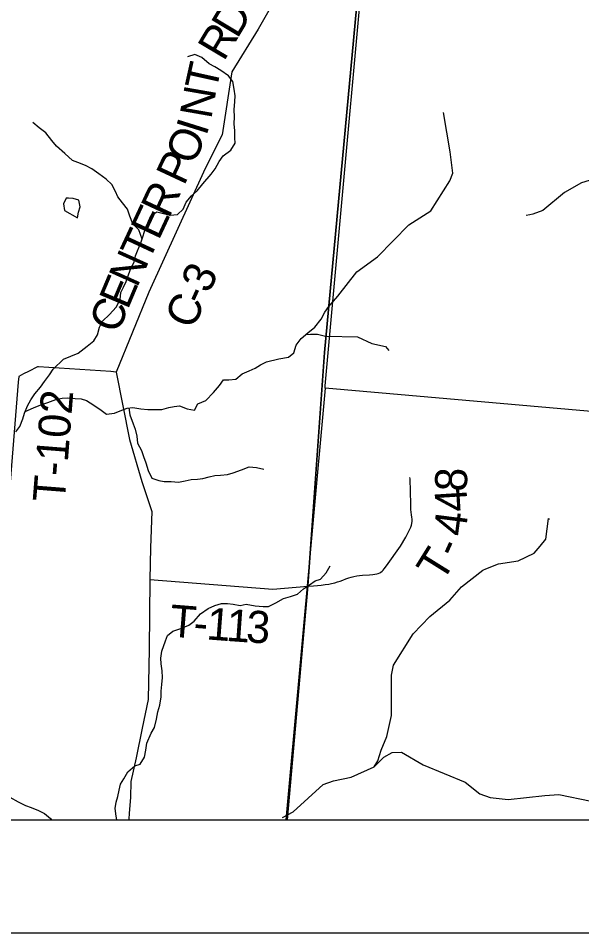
# Model space of a CAD drawing. Extents: x 0 to 42, y 0 to 22.
# Drawn here: x 7.812 to 8.311, y 14 to 14.81 of the extents above; entities that cross this region are included whole.
import ezdxf

# ---------------------------------------------------------------- set-up
doc = ezdxf.new("R2010")
doc.units = 0
for name, color, linetype in [('GM_X_County_Road', 7, 'Continuous'), ('GM_X_County_Road_Text', 7, 'Continuous'), ('GM_X_Minor_Lake', 7, 'Continuous'), ('GM_X_Minor_River', 7, 'Continuous'), ('GM_X_Section', 7, 'Continuous'), ('GM_X_Township_Road', 7, 'Continuous'), ('GM_X_Township_Road_Text', 7, 'Continuous'), ('GM_X_Unincorporated', 7, 'Continuous'), ('SH_Cut_Line', 7, 'Continuous'), ('SH_Data', 7, 'Continuous')]:
    doc.layers.add(name, color=color, linetype=linetype)

msp = doc.modelspace()

# ---------------------------------------------------------------- linework, layer by layer
at = {"layer": 'GM_X_County_Road'}
msp.add_lwpolyline([(8.04723, 14.83957), (8.0246, 14.79994), (8.00131, 14.76235), (7.99271, 14.70653), (7.97771, 14.67652), (7.92772, 14.56724), (7.89891, 14.49644), (7.91067, 14.43677), (7.92151, 14.39947), (7.93053, 14.37298), (7.92917, 14.34086), (7.92863, 14.31266), (7.92805, 14.25119), (7.9272, 14.20636), (7.92197, 14.18103), (7.91656, 14.15495), (7.91186, 14.13381), (7.91144, 14.11975), (7.91045, 14.10587), (7.90994, 14.10055), (7.91011, 14.1)], dxfattribs=at)
at = {"layer": 'GM_X_Minor_Lake'}
for points in [[(7.85646, 14.65026), (7.8546, 14.65038), (7.85197, 14.64544), (7.85292, 14.63937), (7.86447, 14.63295)], [(7.86447, 14.63295), (7.86541, 14.63807), (7.86691, 14.64282), (7.86558, 14.64869), (7.86066, 14.65001), (7.85646, 14.65026)]]:
    msp.add_lwpolyline(points, dxfattribs=at)
at = {"layer": 'GM_X_Minor_River'}
for points in [[(7.86526, 14.51323), (7.87301, 14.51935), (7.87905, 14.52391), (7.88226, 14.52923), (7.88414, 14.53606), (7.88677, 14.54138), (7.893, 14.54746), (7.89866, 14.55373), (7.90225, 14.56057), (7.90299, 14.56683), (7.90544, 14.57157), (7.9077, 14.5767), (7.90958, 14.58239), (7.91222, 14.58885), (7.91486, 14.5936), (7.91598, 14.59929), (7.92087, 14.61163), (7.92276, 14.61694), (7.92444, 14.62302), (7.92746, 14.63004), (7.92953, 14.63479), (7.93482, 14.63821), (7.94655, 14.6352), (7.95317, 14.63597), (7.95827, 14.64053), (7.96071, 14.6468), (7.96562, 14.65231), (7.97053, 14.65687), (7.97562, 14.66314), (7.98298, 14.6715), (7.98657, 14.67625), (7.98996, 14.6829), (7.99354, 14.68783), (8.00034, 14.69278), (8.0043, 14.69905), (8.00411, 14.70379), (8.00409, 14.70986), (8.00333, 14.71631), (8.00369, 14.72238), (8.00349, 14.72844), (8.00386, 14.73603), (8.00423, 14.74097), (8.00346, 14.74684), (8.00231, 14.75367), (7.99833, 14.75878), (7.99151, 14.76332), (7.98621, 14.76654), (7.9811, 14.76937), (7.97466, 14.77486), (7.96841, 14.7775), (7.96198, 14.7754)], [(8.08738, 14.55438), (8.09512, 14.5635), (8.11201, 14.58521), (8.13034, 14.59835), (8.15829, 14.62662), (8.17776, 14.63918), (8.19451, 14.66583), (8.19722, 14.67264), (8.19493, 14.69147), (8.18881, 14.72609)], [(7.92179, 14.6142), (7.91877, 14.62244), (7.91347, 14.62755), (7.91081, 14.63456), (7.9089, 14.64062), (7.90454, 14.64612), (7.90018, 14.65142), (7.89809, 14.65634), (7.89506, 14.66241), (7.88994, 14.66714), (7.8835, 14.67187), (7.87725, 14.67622), (7.87176, 14.67943), (7.86495, 14.68188), (7.86003, 14.68377), (7.85321, 14.68983), (7.84582, 14.69645), (7.84184, 14.70137), (7.83653, 14.70819), (7.83047, 14.71273), (7.82498, 14.71727)], [(8.32187, 14.66733), (8.31109, 14.6639), (8.29616, 14.65534), (8.27707, 14.63956), (8.26818, 14.63632), (8.26534, 14.63555), (8.26232, 14.63498)], [(8.05628, 14.51336), (8.05835, 14.52029), (8.06288, 14.52599), (8.06854, 14.53113), (8.07478, 14.53626), (8.08044, 14.5431), (8.08383, 14.54937), (8.08738, 14.55438)], [(8.06698, 14.52971), (8.071, 14.52999), (8.07725, 14.53001), (8.08425, 14.52831), (8.08514, 14.52831)], [(8.08514, 14.52831), (8.1128, 14.52764), (8.12545, 14.52184), (8.13757, 14.51908), (8.14057, 14.51564)], [(7.8099, 14.4436), (7.81351, 14.44835), (7.81616, 14.45499), (7.81749, 14.45992), (7.82034, 14.46637), (7.82318, 14.47168), (7.82679, 14.477), (7.83172, 14.48307), (7.83532, 14.488), (7.83969, 14.49408), (7.84291, 14.49901), (7.85203, 14.50771), (7.86526, 14.51323)], [(7.81815, 14.46141), (7.82546, 14.46486), (7.8319, 14.46732), (7.83816, 14.46941), (7.84537, 14.47207), (7.85087, 14.47321), (7.85561, 14.47359), (7.86243, 14.47303), (7.86774, 14.47265), (7.87248, 14.47113), (7.87912, 14.46715), (7.88537, 14.4626), (7.8903, 14.459), (7.89732, 14.45995), (7.90395, 14.46261), (7.90869, 14.46451), (7.91344, 14.46508), (7.92064, 14.46395), (7.9269, 14.46338), (7.93922, 14.46338), (7.94548, 14.46491), (7.95022, 14.46585), (7.95496, 14.46643), (7.9616, 14.46377), (7.96823, 14.46264), (7.97108, 14.46833), (7.97828, 14.47137), (7.98492, 14.47839), (7.99042, 14.48465), (7.99402, 14.48959), (7.99877, 14.4894), (8.00483, 14.49016), (8.01033, 14.49472), (8.01678, 14.49737), (8.02209, 14.49984), (8.02683, 14.50269), (8.03195, 14.50554), (8.04293, 14.50803), (8.05154, 14.50952), (8.05628, 14.51336)], [(7.90998, 14.46466), (7.91097, 14.45844), (7.914, 14.45066), (7.91571, 14.44592), (7.91703, 14.43966), (7.9176, 14.4334), (7.9212, 14.42695), (7.92309, 14.42164), (7.92499, 14.41595), (7.92707, 14.40912), (7.93048, 14.40249), (7.93655, 14.4004), (7.94148, 14.39965), (7.94755, 14.39946), (7.954, 14.39889), (7.96006, 14.40003), (7.96518, 14.40117), (7.97087, 14.40155), (7.97561, 14.40213), (7.98111, 14.40365), (7.98623, 14.40479), (7.99116, 14.40498), (7.99742, 14.40574), (8.00254, 14.40726), (8.00993, 14.40973), (8.01657, 14.41239), (8.0232, 14.41201), (8.02965, 14.41031)], [(8.04623, 14.1021), (8.05564, 14.1071), (8.08239, 14.13117), (8.09156, 14.13455), (8.10699, 14.13769), (8.12759, 14.14676), (8.13082, 14.15225), (8.13355, 14.16159), (8.13857, 14.17382), (8.14287, 14.19219), (8.14285, 14.22799), (8.1446, 14.23702), (8.1619, 14.2646), (8.17665, 14.27997), (8.19456, 14.29437), (8.20488, 14.30624), (8.22377, 14.32095), (8.22633, 14.3223), (8.23767, 14.32667), (8.25496, 14.3293), (8.26912, 14.33595), (8.27468, 14.34224), (8.27967, 14.34838), (8.28188, 14.36689), (8.28293, 14.36609)], [(8.06475, 14.30448), (8.0702, 14.30807), (8.07513, 14.31149), (8.07987, 14.31301), (8.0848, 14.31851), (8.08841, 14.32478)], [(7.89952, 14.1), (7.89875, 14.10312), (7.89799, 14.10995), (7.89894, 14.11545), (7.90027, 14.12058), (7.90159, 14.12608), (7.90254, 14.13139), (7.90558, 14.13613), (7.90918, 14.14258), (7.91525, 14.14771), (7.91999, 14.14923), (7.92379, 14.1553), (7.92512, 14.16175), (7.92606, 14.16782), (7.92967, 14.17674), (7.9327, 14.18167), (7.9346, 14.18907), (7.93574, 14.19552), (7.93745, 14.20159), (7.93859, 14.2088), (7.93878, 14.21392), (7.93916, 14.21981), (7.93973, 14.22588), (7.93954, 14.23195), (7.9386, 14.23821), (7.93841, 14.24295), (7.93936, 14.24921), (7.94239, 14.25832), (7.94429, 14.26306), (7.94903, 14.26686), (7.95605, 14.26933), (7.96325, 14.27217), (7.968, 14.27597), (7.9735, 14.28242), (7.98032, 14.28717), (7.9862, 14.28964), (7.99208, 14.29135), (7.99758, 14.29154), (8.00251, 14.29097), (8.00876, 14.28984), (8.01388, 14.29079), (8.02204, 14.28946), (8.02905, 14.28871), (8.03379, 14.2889), (8.04024, 14.29194), (8.04707, 14.29592), (8.05332, 14.29763), (8.05958, 14.29972), (8.06475, 14.30448)], [(8.12783, 14.14717), (8.13599, 14.15552), (8.1433, 14.15959), (8.1517, 14.15997), (8.17089, 14.14857), (8.20808, 14.13328), (8.22125, 14.12286), (8.23036, 14.11976), (8.24621, 14.11792), (8.27861, 14.12162), (8.29102, 14.1223), (8.31972, 14.11635), (8.3429, 14.11591), (8.34662, 14.11487), (8.3687, 14.13168), (8.38484, 14.13687), (8.39508, 14.13765)], [(7.78334, 14.11711), (7.7901, 14.12034), (7.79484, 14.12167), (7.79958, 14.12186), (7.80451, 14.11997), (7.81191, 14.1158), (7.81835, 14.11257), (7.82347, 14.11087), (7.82992, 14.10822), (7.83542, 14.10556), (7.84053, 14.10101), (7.84155, 14.1)]]:
    msp.add_lwpolyline(points, dxfattribs=at)
at = {"layer": 'GM_X_Section'}
msp.add_lwpolyline([(8.13021, 14.99178), (8.69178, 14.94189), (8.64678, 14.43282), (8.0839, 14.48217), (8.08411, 14.48421), (8.12984, 14.9874)], close=True, dxfattribs=at)
at = {"layer": 'GM_X_Township_Road'}
msp.add_lwpolyline([(8.05023, 14.1), (8.9, 14.1), (8.9, 16.95771), (8.669, 16.9761), (8.30518, 17.00518), (8.2967, 17.00562), (8.26133, 16.54947), (8.24231, 16.32059), (8.17227, 15.49063), (8.16983, 15.46634), (8.16945, 15.45935), (8.16837, 15.44612), (8.1628, 15.37905), (8.15761, 15.31908), (8.1512, 15.24132), (8.08338, 14.51358), (8.06868, 14.30702)], close=True, dxfattribs=at)
for points in [[(4.80642, 14.1), (8.05023, 14.1), (8.06868, 14.30702), (8.08338, 14.51358), (8.1512, 15.24132), (8.15761, 15.31908), (8.1628, 15.37905), (8.16837, 15.44612), (8.16945, 15.45935), (8.16983, 15.46634), (8.17227, 15.49063), (8.24231, 16.32059)], [(7.89891, 14.49644), (7.89399, 14.49677), (7.83003, 14.50104), (7.82919, 14.5011), (7.82116, 14.49698), (7.81677, 14.49473), (7.81249, 14.49254), (7.81208, 14.4875), (7.80134, 14.35479)], [(8.06879, 14.30676), (8.07355, 14.30725), (8.07717, 14.30756), (8.08057, 14.30783), (8.0841, 14.30819), (8.08717, 14.3086), (8.08977, 14.30912), (8.09261, 14.30983), (8.09498, 14.31053), (8.09731, 14.31135), (8.09964, 14.3122), (8.10239, 14.31335), (8.10491, 14.31426), (8.10713, 14.31493), (8.10941, 14.31549), (8.11207, 14.31596), (8.11444, 14.31625), (8.11721, 14.31643), (8.12328, 14.31679), (8.12629, 14.3171), (8.12816, 14.31733), (8.12971, 14.31768), (8.13115, 14.31812), (8.13237, 14.31868), (8.13346, 14.31932), (8.13445, 14.32014), (8.13536, 14.32102), (8.13629, 14.32204), (8.13848, 14.32495), (8.15073, 14.34218), (8.15549, 14.35026), (8.15992, 14.35901), (8.16059, 14.36073), (8.16098, 14.36237), (8.16117, 14.36432), (8.16113, 14.36607), (8.16094, 14.36798), (8.16063, 14.37001), (8.16028, 14.37223), (8.16, 14.37461), (8.15989, 14.37687), (8.15986, 14.37937), (8.15922, 14.40186), (8.15919, 14.40318)], [(7.92863, 14.31266), (8.03773, 14.30409), (8.06879, 14.30676)]]:
    msp.add_lwpolyline(points, dxfattribs=at)
at = {"layer": 'GM_X_Unincorporated'}
msp.add_lwpolyline([(8.04916, 14.1), (8.60693, 14.1), (8.64678, 14.43282), (8.0839, 14.48217)], close=True, dxfattribs=at)
at = {"layer": 'SH_Cut_Line'}
for points in [[(2.1, 20.9), (2.1, 14.1), (8.05023, 14.1), (8.06868, 14.30702), (8.08338, 14.51358), (8.1512, 15.24132), (8.15761, 15.31908), (8.1628, 15.37905), (8.16837, 15.44612), (8.16945, 15.45935), (8.16983, 15.46634), (8.17227, 15.49063), (8.24231, 16.32059)], [(8.24231, 16.32059), (8.17227, 15.49063), (8.16983, 15.46634), (8.16945, 15.45935), (8.16837, 15.44612), (8.1628, 15.37905), (8.15761, 15.31908), (8.1512, 15.24132), (8.08338, 14.51358), (8.06868, 14.30702), (8.05023, 14.1), (8.9, 14.1), (8.9, 20.00639)]]:
    msp.add_lwpolyline(points, dxfattribs=at)
at = {"layer": 'SH_Data'}
for p, q in [((2.1, 14.1), (8.9, 14.1)), ((2, 14), (9, 14))]:
    msp.add_line(p, q, dxfattribs=at)

# ---------------------------------------------------------------- texts
at = {"layer": 'GM_X_County_Road_Text'}
for s, rotation, p in [('D', 58.98626, (8.00606, 14.79078)), ('R', 59.33477, (7.99418, 14.77075)), ('T', 77.48048, (7.98729, 14.74405)), ('N', 80.08053, (7.98305, 14.71976)), ('I', 72.60729, (7.97861, 14.7047)), ('O', 66.23226, (7.96732, 14.67859)), ('P', 64.9929, (7.95894, 14.66061)), ('R', 64.9939, (7.94538, 14.63153)), ('E', 64.99139, (7.93639, 14.61227)), ('T', 65.01054, (7.92742, 14.59301)), ('N', 65.7749, (7.9172, 14.5703)), ('3', 65.42985, (7.98102, 14.56508)), ('E', 67.15761, (7.90902, 14.55088)), ('C', 66.9454, (7.96716, 14.53316)), ('-', 65.68007, (7.97623, 14.55447)), ('C', 67.88332, (7.90027, 14.52936))]:
    msp.add_text(s, height=0.02841, rotation=rotation, dxfattribs=at).set_placement(p)
at = {"layer": 'GM_X_Township_Road_Text'}
for s, height, rotation, p in [('T-102', 0.028409, 85.51568, (7.85312, 14.38046)), ('8', 0.02841, 87.53519, (8.20943, 14.3901)), ('4', 0.02841, 93.56659, (8.21051, 14.37343)), ('4', 0.02841, 82.7682, (8.20812, 14.35024)), ('T', 0.02841, 58.05866, (8.18762, 14.30909)), ('-', 0.02841, 65.6141, (8.20079, 14.33073)), ('T', 0.02841, 355.51343, (7.94548, 14.26231)), ('1', 0.02841, 355.65349, (7.97822, 14.25975)), ('1', 0.02841, 355.90663, (7.99567, 14.25842)), ('3', 0.02841, 356.82205, (8.01348, 14.25715)), ('-', 0.02841, 355.53529, (7.96663, 14.26065))]:
    msp.add_text(s, height=height, rotation=rotation, dxfattribs=at).set_placement(p)

doc.saveas('drawing.dxf')
